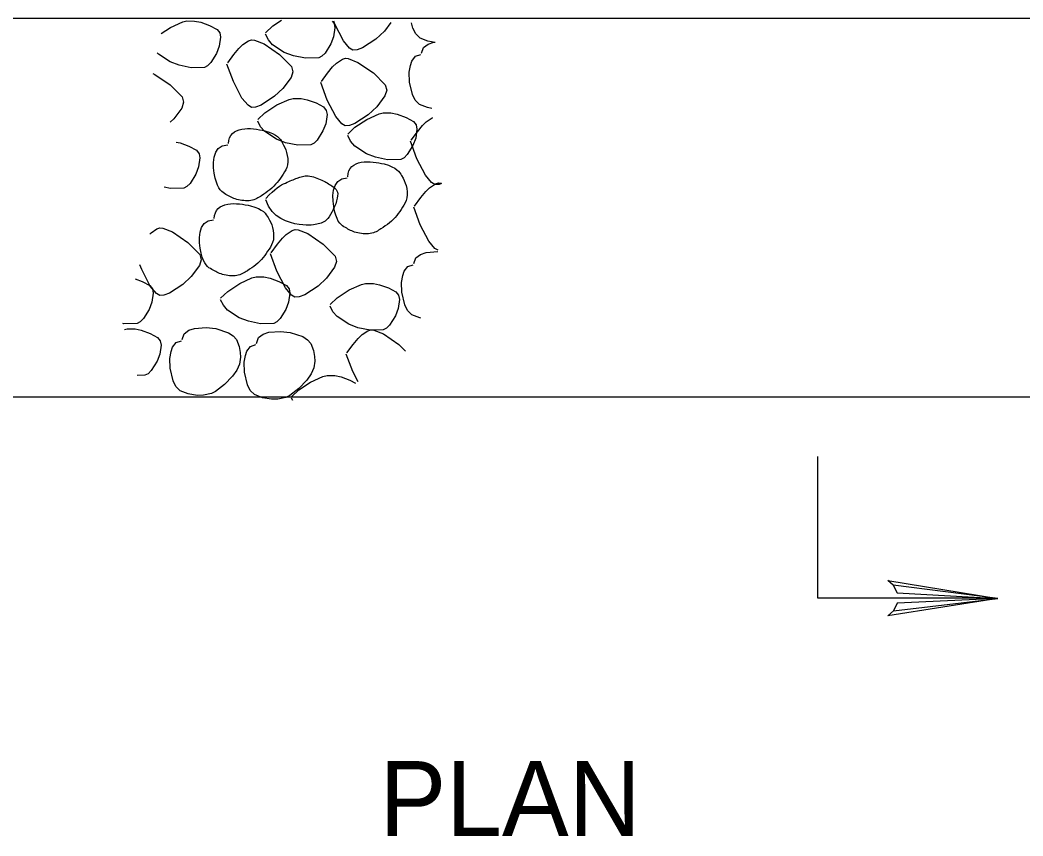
# Model space of a CAD drawing. Extents: x 636462 to 638208, y 299350 to 300538.
# Drawn here: x 637731.8 to 637790.4, y 299698.3 to 299746 of the extents above; entities that cross this region are included whole.
import ezdxf

# ---------------------------------------------------------------- set-up
doc = ezdxf.new("R2010")
doc.units = 0
doc.layers.add('Default', color=7, linetype='Continuous')

# ---------------------------------------------------------------- blocks, each defined once
blk = doc.blocks.new('SC9446')
at = {"layer": 'Default'}
blk.add_line((0, 0), (0, 0), dxfattribs=at)

msp = doc.modelspace()

# ---------------------------------------------------------------- linework, layer by layer
at = {"layer": 'Default'}
for p, q in [((637740.02, 299745.161), (637740.557, 299745.518)), ((637740.557, 299745.518), (637741.275, 299745.843)), ((637741.275, 299745.843), (637741.513, 299745.901)), ((637741.513, 299745.901), (637741.971, 299745.896)), ((637741.971, 299745.896), (637742.33, 299745.822)), ((637742.33, 299745.822), (637742.851, 299745.633)), ((637742.851, 299745.633), (637743.286, 299745.396)), ((637746.121, 299745.214), (637746.536, 299745.613)), ((637746.536, 299745.613), (637747.038, 299745.944)), ((637750.014, 299745.882), (637750.115, 299745.756)), ((637750.164, 299745.507), (637750.088, 299744.977)), ((637750.164, 299745.703), (637750.097, 299745.88)), ((637750.115, 299745.756), (637750.164, 299745.507)), ((637750.666, 299744.742), (637750.164, 299745.703)), ((637753.439, 299745.811), (637753.061, 299745.3)), ((637754.717, 299745.475), (637754.643, 299745.786)), ((637754.887, 299745.143), (637754.717, 299745.475)), ((637743.286, 299745.396), (637743.44, 299745.2)), ((637743.489, 299744.952), (637743.413, 299744.422)), ((637743.44, 299745.2), (637743.489, 299744.952)), ((637746.283, 299744.8), (637746.121, 299745.124)), ((637750.088, 299744.977), (637749.929, 299744.558)), ((637753.061, 299745.3), (637752.563, 299744.843)), ((637755.138, 299744.894), (637754.887, 299745.143)), ((637755.592, 299744.71), (637755.138, 299744.894)), ((637743.413, 299744.422), (637743.254, 299744.003)), ((637744.263, 299743.936), (637744.555, 299744.288)), ((637744.555, 299744.288), (637744.781, 299744.516)), ((637744.781, 299744.516), (637745.126, 299744.744)), ((637745.126, 299744.744), (637745.297, 299744.793)), ((637745.297, 299744.793), (637745.465, 299744.786)), ((637745.465, 299744.786), (637746.029, 299744.558)), ((637746.029, 299744.558), (637746.932, 299743.938)), ((637746.529, 299744.514), (637746.283, 299744.8)), ((637747.211, 299744.067), (637746.529, 299744.514)), ((637749.929, 299744.558), (637749.592, 299744.019)), ((637751.018, 299744.316), (637750.666, 299744.742)), ((637751.214, 299744.201), (637751.018, 299744.316)), ((637751.785, 299744.332), (637751.458, 299744.208)), ((637752.563, 299744.843), (637751.785, 299744.332)), ((637755.228, 299744.012), (637755.35, 299744.348)), ((637755.35, 299744.348), (637755.618, 299744.551)), ((637756.016, 299744.641), (637755.592, 299744.71)), ((637755.618, 299744.551), (637755.942, 299744.662)), ((637755.942, 299744.662), (637756.016, 299744.666)), ((637739.854, 299743.959), (637739.783, 299744.042)), ((637740.536, 299743.515), (637739.854, 299743.959)), ((637743.254, 299744.003), (637742.918, 299743.464)), ((637743.903, 299743.445), (637744.263, 299743.936)), ((637746.932, 299743.938), (637747.63, 299743.245)), ((637747.741, 299743.867), (637747.211, 299744.067)), ((637748.448, 299743.717), (637747.741, 299743.867)), ((637749.224, 299743.74), (637748.448, 299743.717)), ((637749.408, 299743.837), (637749.224, 299743.74)), ((637749.592, 299744.019), (637749.408, 299743.837)), ((637750.606, 299743.669), (637750.776, 299743.717)), ((637750.776, 299743.717), (637750.947, 299743.71)), ((637750.947, 299743.71), (637751.511, 299743.482)), ((637751.458, 299744.208), (637751.214, 299744.201)), ((637754.666, 299743.561), (637754.878, 299743.837)), ((637754.878, 299743.837), (637755.182, 299743.945)), ((637741.066, 299743.312), (637740.536, 299743.515)), ((637741.773, 299743.162), (637741.066, 299743.312)), ((637742.549, 299743.185), (637741.773, 299743.162)), ((637742.731, 299743.282), (637742.549, 299743.185)), ((637742.918, 299743.464), (637742.731, 299743.282)), ((637744.237, 299742.358), (637743.857, 299743.379)), ((637747.63, 299743.245), (637747.713, 299742.93)), ((637749.742, 299742.86), (637750.035, 299743.215)), ((637750.035, 299743.215), (637750.263, 299743.441)), ((637750.263, 299743.441), (637750.606, 299743.669)), ((637751.511, 299743.482), (637752.414, 299742.865)), ((637754.512, 299742.911), (637754.576, 299743.307)), ((637754.576, 299743.307), (637754.666, 299743.561)), ((637739.527, 299742.828), (637739.649, 299742.78)), ((637739.649, 299742.78), (637740.552, 299742.16)), ((637747.607, 299742.596), (637747.132, 299741.955)), ((637747.713, 299742.93), (637747.607, 299742.596)), ((637749.383, 299742.37), (637749.742, 299742.86)), ((637752.414, 299742.865), (637753.112, 299742.169)), ((637754.524, 299742.333), (637754.512, 299742.911)), ((637740.552, 299742.16), (637741.25, 299741.465)), ((637744.739, 299741.398), (637744.237, 299742.358)), ((637747.132, 299741.955), (637746.637, 299741.499)), ((637749.717, 299741.283), (637749.339, 299742.303)), ((637753.112, 299742.169), (637753.192, 299741.854)), ((637754.696, 299741.601), (637754.524, 299742.333)), ((637741.25, 299741.465), (637741.331, 299741.151)), ((637745.092, 299740.972), (637744.739, 299741.398)), ((637746.637, 299741.499), (637745.859, 299740.988)), ((637747.494, 299741.322), (637747.729, 299741.379)), ((637747.729, 299741.379), (637748.19, 299741.375)), ((637748.19, 299741.375), (637748.549, 299741.301)), ((637753.086, 299741.52), (637752.614, 299740.88)), ((637753.192, 299741.854), (637753.086, 299741.52)), ((637754.864, 299741.269), (637754.696, 299741.601)), ((637741.225, 299740.815), (637740.753, 299740.177)), ((637741.331, 299741.151), (637741.225, 299740.815)), ((637745.288, 299740.854), (637745.092, 299740.972)), ((637745.529, 299740.861), (637745.288, 299740.854)), ((637745.859, 299740.988), (637745.529, 299740.861)), ((637746.08, 299740.536), (637746.775, 299740.997)), ((637746.775, 299740.997), (637747.494, 299741.322)), ((637748.549, 299741.301), (637749.067, 299741.112)), ((637749.067, 299741.112), (637749.502, 299740.875)), ((637749.502, 299740.875), (637749.659, 299740.679)), ((637750.219, 299740.322), (637749.717, 299741.283)), ((637752.614, 299740.88), (637752.117, 299740.424)), ((637755.115, 299741.02), (637754.864, 299741.269)), ((637755.569, 299740.836), (637755.115, 299741.02)), ((637755.823, 299740.794), (637755.569, 299740.836)), ((637740.753, 299740.177), (637740.552, 299739.993)), ((637745.663, 299740.138), (637746.08, 299740.536)), ((637749.705, 299740.433), (637749.629, 299739.901)), ((637749.659, 299740.679), (637749.705, 299740.433)), ((637750.571, 299739.896), (637750.219, 299740.322)), ((637752.117, 299740.424), (637751.34, 299739.912)), ((637752.029, 299740.147), (637752.75, 299740.472)), ((637752.75, 299740.472), (637752.985, 299740.532)), ((637752.985, 299740.532), (637753.443, 299740.527)), ((637753.443, 299740.527), (637753.805, 299740.451)), ((637753.805, 299740.451), (637754.323, 299740.262)), ((637754.323, 299740.262), (637754.758, 299740.025)), ((637755.505, 299740.011), (637755.848, 299740.239)), ((637755.848, 299740.239), (637755.894, 299740.253)), ((637745.824, 299739.723), (637745.663, 299740.048)), ((637746.073, 299739.438), (637745.824, 299739.723)), ((637749.629, 299739.901), (637749.47, 299739.482)), ((637750.767, 299739.781), (637750.571, 299739.896)), ((637751.011, 299739.786), (637750.767, 299739.781)), ((637750.919, 299739.29), (637751.334, 299739.687)), ((637751.34, 299739.912), (637751.011, 299739.786)), ((637751.334, 299739.687), (637752.029, 299740.147)), ((637754.758, 299740.025), (637754.913, 299739.829)), ((637754.961, 299739.583), (637754.885, 299739.053)), ((637754.913, 299739.829), (637754.961, 299739.583)), ((637754.986, 299739.431), (637755.277, 299739.786)), ((637755.277, 299739.786), (637755.505, 299740.011)), ((637746.755, 299738.993), (637746.073, 299739.438)), ((637747.284, 299738.791), (637746.755, 299738.993)), ((637749.47, 299739.482), (637749.136, 299738.943)), ((637751.08, 299738.876), (637750.919, 299739.201)), ((637754.625, 299738.94), (637754.986, 299739.431)), ((637754.885, 299739.053), (637754.726, 299738.634)), ((637740.886, 299738.821), (637741.123, 299738.772)), ((637741.123, 299738.772), (637741.642, 299738.581)), ((637741.642, 299738.581), (637742.077, 299738.346)), ((637747.992, 299738.641), (637747.284, 299738.791)), ((637748.768, 299738.664), (637747.992, 299738.641)), ((637748.95, 299738.761), (637748.768, 299738.664)), ((637749.136, 299738.943), (637748.95, 299738.761)), ((637751.327, 299738.59), (637751.08, 299738.876)), ((637752.008, 299738.143), (637751.327, 299738.59)), ((637754.726, 299738.634), (637754.392, 299738.095)), ((637754.959, 299737.853), (637754.581, 299738.874)), ((637742.077, 299738.346), (637742.234, 299738.148)), ((637742.28, 299737.902), (637742.204, 299737.372)), ((637742.234, 299738.148), (637742.28, 299737.902)), ((637752.538, 299737.941), (637752.008, 299738.143)), ((637753.248, 299737.791), (637752.538, 299737.941)), ((637754.021, 299737.816), (637753.248, 299737.791)), ((637754.206, 299737.911), (637754.021, 299737.816)), ((637754.392, 299738.095), (637754.206, 299737.911)), ((637755.461, 299736.893), (637754.959, 299737.853)), ((637742.204, 299737.372), (637742.045, 299736.953)), ((637742.045, 299736.953), (637741.711, 299736.414)), ((637755.813, 299736.467), (637755.461, 299736.893)), ((637740.566, 299736.112), (637740.186, 299736.19)), ((637741.34, 299736.135), (637740.566, 299736.112)), ((637741.524, 299736.232), (637741.34, 299736.135)), ((637741.711, 299736.414), (637741.524, 299736.232)), ((637755.472, 299735.932), (637755.7, 299736.158)), ((637755.7, 299736.158), (637756.044, 299736.388)), ((637756.009, 299736.351), (637755.813, 299736.467)), ((637756.253, 299736.356), (637756.009, 299736.351)), ((637756.044, 299736.388), (637756.214, 299736.437)), ((637756.214, 299736.437), (637756.385, 299736.43)), ((637756.396, 299736.411), (637756.253, 299736.356)), ((637756.385, 299736.43), (637756.394, 299736.425)), ((637754.821, 299735.089), (637755.182, 299735.58)), ((637755.182, 299735.58), (637755.472, 299735.932)), ((637755.155, 299734.002), (637754.777, 299735.023)), ((637739.428, 299733.532), (637739.771, 299733.76)), ((637739.771, 299733.76), (637739.944, 299733.809)), ((637739.944, 299733.809), (637740.112, 299733.802)), ((637740.112, 299733.802), (637740.677, 299733.574)), ((637755.657, 299733.042), (637755.155, 299734.002)), ((637739.352, 299733.456), (637739.428, 299733.532)), ((637740.677, 299733.574), (637741.579, 299732.957)), ((637746.808, 299732.855), (637747.1, 299733.208)), ((637747.1, 299733.208), (637747.328, 299733.433)), ((637747.328, 299733.433), (637747.671, 299733.664)), ((637747.671, 299733.664), (637747.842, 299733.71)), ((637747.842, 299733.71), (637748.012, 299733.703)), ((637748.012, 299733.703), (637748.577, 299733.477)), ((637748.577, 299733.477), (637749.479, 299732.858)), ((637741.579, 299732.957), (637742.277, 299732.261)), ((637746.448, 299732.362), (637746.808, 299732.855)), ((637749.479, 299732.858), (637750.177, 299732.162)), ((637756.009, 299732.616), (637755.657, 299733.042)), ((637756.196, 299732.505), (637756.009, 299732.616)), ((637742.277, 299732.261), (637742.36, 299731.945)), ((637746.782, 299731.277), (637746.405, 299732.296)), ((637750.177, 299732.162), (637750.258, 299731.849)), ((637754.777, 299731.729), (637754.897, 299732.065)), ((637754.897, 299732.065), (637755.166, 299732.268)), ((637755.166, 299732.268), (637755.491, 299732.376)), ((637755.491, 299732.376), (637756.186, 299732.431)), ((637738.885, 299731.374), (637738.776, 299731.664)), ((637739.384, 299730.414), (637738.885, 299731.374)), ((637742.254, 299731.611), (637741.78, 299730.971)), ((637742.36, 299731.945), (637742.254, 299731.611)), ((637750.152, 299731.512), (637749.68, 299730.874)), ((637750.258, 299731.849), (637750.152, 299731.512)), ((637754.215, 299731.277), (637754.427, 299731.554)), ((637754.427, 299731.554), (637754.731, 299731.662)), ((637738.509, 299730.831), (637738.917, 299730.683)), ((637741.78, 299730.971), (637741.285, 299730.515)), ((637744.604, 299730.568), (637745.322, 299730.893)), ((637745.322, 299730.893), (637745.559, 299730.95)), ((637745.559, 299730.95), (637746.018, 299730.946)), ((637746.018, 299730.946), (637746.379, 299730.872)), ((637746.379, 299730.872), (637746.898, 299730.683)), ((637747.284, 299730.317), (637746.782, 299731.277)), ((637749.68, 299730.874), (637749.182, 299730.416)), ((637754.061, 299730.628), (637754.125, 299731.024)), ((637754.125, 299731.024), (637754.215, 299731.277)), ((637738.917, 299730.683), (637739.352, 299730.446)), ((637739.352, 299730.446), (637739.506, 299730.25)), ((637739.739, 299729.988), (637739.384, 299730.414)), ((637739.506, 299730.25), (637739.555, 299730.004)), ((637741.285, 299730.515), (637740.506, 299730.004)), ((637743.908, 299730.107), (637744.604, 299730.568)), ((637746.898, 299730.683), (637747.333, 299730.446)), ((637747.637, 299729.891), (637747.284, 299730.317)), ((637747.333, 299730.446), (637747.487, 299730.25)), ((637747.487, 299730.25), (637747.536, 299730.004)), ((637749.182, 299730.416), (637748.406, 299729.905)), ((637751.002, 299730.193), (637751.72, 299730.517)), ((637751.72, 299730.517), (637751.958, 299730.575)), ((637751.958, 299730.575), (637752.416, 299730.57)), ((637752.416, 299730.57), (637752.775, 299730.497)), ((637752.775, 299730.497), (637753.296, 299730.308)), ((637753.296, 299730.308), (637753.731, 299730.071)), ((637754.072, 299730.05), (637754.061, 299730.628)), ((637739.555, 299730.004), (637739.479, 299729.472)), ((637739.933, 299729.87), (637739.739, 299729.988)), ((637740.177, 299729.877), (637739.933, 299729.87)), ((637740.506, 299730.004), (637740.177, 299729.877)), ((637743.493, 299729.709), (637743.908, 299730.107)), ((637743.655, 299729.294), (637743.493, 299729.619)), ((637747.536, 299730.004), (637747.46, 299729.472)), ((637747.833, 299729.773), (637747.637, 299729.891)), ((637748.077, 299729.78), (637747.833, 299729.773)), ((637748.406, 299729.905), (637748.077, 299729.78)), ((637749.889, 299729.334), (637750.306, 299729.732)), ((637750.306, 299729.732), (637751.002, 299730.193)), ((637753.731, 299730.071), (637753.886, 299729.875)), ((637753.934, 299729.628), (637753.858, 299729.096)), ((637753.886, 299729.875), (637753.934, 299729.628)), ((637754.243, 299729.317), (637754.072, 299730.05)), ((637739.32, 299729.053), (637738.986, 299728.514)), ((637739.479, 299729.472), (637739.32, 299729.053)), ((637743.901, 299729.009), (637743.655, 299729.294)), ((637747.301, 299729.053), (637746.967, 299728.514)), ((637747.46, 299729.472), (637747.301, 299729.053)), ((637750.051, 299728.919), (637749.889, 299729.244)), ((637753.858, 299729.096), (637753.699, 299728.677)), ((637754.413, 299728.983), (637754.243, 299729.317)), ((637738.986, 299728.514), (637738.799, 299728.332)), ((637744.583, 299728.564), (637743.901, 299729.009)), ((637745.113, 299728.362), (637744.583, 299728.564)), ((637746.967, 299728.514), (637746.78, 299728.332)), ((637750.299, 299728.633), (637750.051, 299728.919)), ((637750.981, 299728.189), (637750.299, 299728.633)), ((637753.699, 299728.677), (637753.363, 299728.138)), ((637754.664, 299728.737), (637754.413, 299728.983)), ((637755.118, 299728.553), (637754.664, 299728.737)), ((637755.191, 299728.541), (637755.118, 299728.553)), ((637737.839, 299728.212), (637737.779, 299728.226)), ((637738.615, 299728.235), (637737.839, 299728.212)), ((637737.876, 299727.878), (637738.035, 299727.919)), ((637738.035, 299727.919), (637738.495, 299727.915)), ((637738.495, 299727.915), (637738.855, 299727.839)), ((637738.799, 299728.332), (637738.615, 299728.235)), ((637741.635, 299727.832), (637741.962, 299727.94)), ((637741.962, 299727.94), (637742.655, 299727.995)), ((637742.655, 299727.995), (637743.21, 299727.931)), ((637743.21, 299727.931), (637743.954, 299727.689)), ((637745.822, 299728.212), (637745.113, 299728.362)), ((637746.596, 299728.235), (637745.822, 299728.212)), ((637746.78, 299728.332), (637746.596, 299728.235)), ((637751.511, 299727.986), (637750.981, 299728.189)), ((637752.218, 299727.836), (637751.511, 299727.986)), ((637752.994, 299727.86), (637752.218, 299727.836)), ((637753.178, 299727.956), (637752.994, 299727.86)), ((637753.363, 299728.138), (637753.178, 299727.956)), ((637738.855, 299727.839), (637739.373, 299727.65)), ((637739.373, 299727.65), (637739.808, 299727.413)), ((637739.808, 299727.413), (637739.965, 299727.217)), ((637741.245, 299727.293), (637741.368, 299727.629)), ((637741.368, 299727.629), (637741.635, 299727.832)), ((637743.954, 299727.689), (637744.233, 299727.507)), ((637744.233, 299727.507), (637744.417, 299727.293)), ((637744.417, 299727.293), (637744.574, 299726.89)), ((637745.587, 299727.065), (637745.709, 299727.403)), ((637745.709, 299727.403), (637745.976, 299727.604)), ((637745.976, 299727.604), (637746.303, 299727.714)), ((637746.303, 299727.714), (637746.997, 299727.77)), ((637746.997, 299727.77), (637747.552, 299727.705)), ((637747.552, 299727.705), (637748.296, 299727.461)), ((637748.296, 299727.461), (637748.574, 299727.281)), ((637748.574, 299727.281), (637748.759, 299727.065)), ((637751.232, 299726.998), (637751.525, 299727.353)), ((637751.525, 299727.353), (637751.75, 299727.579)), ((637751.75, 299727.579), (637752.094, 299727.807)), ((637752.094, 299727.807), (637752.266, 299727.855)), ((637752.266, 299727.855), (637752.434, 299727.848)), ((637752.434, 299727.848), (637752.999, 299727.62)), ((637752.999, 299727.62), (637753.902, 299727)), ((637740.011, 299726.97), (637739.935, 299726.441)), ((637739.965, 299727.217), (637740.011, 299726.97)), ((637740.594, 299726.588), (637740.686, 299726.841)), ((637740.686, 299726.841), (637740.895, 299727.118)), ((637740.895, 299727.118), (637741.202, 299727.226)), ((637744.574, 299726.89), (637744.636, 299726.535)), ((637745.027, 299726.616), (637745.237, 299726.892)), ((637745.237, 299726.892), (637745.543, 299726.998)), ((637748.759, 299727.065), (637748.915, 299726.662)), ((637750.871, 299726.508), (637751.232, 299726.998)), ((637753.902, 299727), (637754.293, 299726.613)), ((637739.935, 299726.441), (637739.776, 299726.022)), ((637740.531, 299726.192), (637740.594, 299726.588)), ((637740.543, 299725.614), (637740.531, 299726.192)), ((637744.645, 299726.259), (637744.59, 299725.858)), ((637744.636, 299726.535), (637744.645, 299726.259)), ((637744.871, 299725.966), (637744.935, 299726.362)), ((637744.935, 299726.362), (637745.027, 299726.616)), ((637748.915, 299726.662), (637748.977, 299726.307)), ((637748.977, 299726.307), (637748.987, 299726.033)), ((637751.207, 299725.42), (637750.827, 299726.441)), ((637739.776, 299726.022), (637739.442, 299725.483)), ((637740.713, 299724.881), (637740.543, 299725.614)), ((637744.59, 299725.858), (637744.44, 299725.506)), ((637744.885, 299725.388), (637744.871, 299725.966)), ((637748.931, 299725.632), (637748.779, 299725.28)), ((637748.987, 299726.033), (637748.931, 299725.632)), ((637739.071, 299725.204), (637738.622, 299725.19)), ((637739.255, 299725.298), (637739.071, 299725.204)), ((637739.442, 299725.483), (637739.255, 299725.298)), ((637744.177, 299725.149), (637743.714, 299724.663)), ((637744.44, 299725.506), (637744.177, 299725.149)), ((637745.055, 299724.656), (637744.885, 299725.388)), ((637748.779, 299725.28), (637748.519, 299724.923)), ((637748.749, 299724.81), (637749.468, 299725.135)), ((637749.468, 299725.135), (637749.705, 299725.192)), ((637749.705, 299725.192), (637750.164, 299725.188)), ((637750.164, 299725.188), (637750.523, 299725.114)), ((637750.523, 299725.114), (637751.043, 299724.925)), ((637751.518, 299724.822), (637751.207, 299725.42)), ((637740.884, 299724.547), (637740.713, 299724.881)), ((637741.135, 299724.301), (637740.884, 299724.547)), ((637743.714, 299724.663), (637743.189, 299724.255)), ((637745.225, 299724.322), (637745.055, 299724.656)), ((637748.056, 299724.437), (637747.529, 299724.029)), ((637747.637, 299723.951), (637748.054, 299724.349)), ((637748.054, 299724.349), (637748.749, 299724.81)), ((637748.519, 299724.923), (637748.056, 299724.437)), ((637751.043, 299724.925), (637751.373, 299724.746)), ((637741.589, 299724.117), (637741.135, 299724.301)), ((637742.128, 299724.027), (637741.589, 299724.117)), ((637742.498, 299724.034), (637742.128, 299724.027)), ((637742.959, 299724.14), (637742.498, 299724.034)), ((637743.189, 299724.255), (637742.959, 299724.14)), ((637745.476, 299724.073), (637745.225, 299724.322)), ((637745.93, 299723.891), (637745.476, 299724.073)), ((637746.469, 299723.801), (637745.93, 299723.891)), ((637746.838, 299723.808), (637746.469, 299723.801)), ((637747.301, 299723.914), (637746.838, 299723.808)), ((637747.529, 299724.029), (637747.301, 299723.914)), ((637747.701, 299723.734), (637747.637, 299723.861))]:
    msp.add_line(p, q, dxfattribs=at)
for points in [[(637698.562, 299746.05), (637698.562, 299723.939), (637836.756, 299723.939), (637836.756, 299746.05), (637698.562, 299746.05)], [(637788.617, 299712.179), (637778.373, 299712.179), (637778.373, 299720.471)], [(637782.782, 299712.944), (637783.009, 299712.502), (637788.884, 299712.177), (637782.782, 299712.944), (637782.469, 299713.211), (637788.884, 299712.177), (637783.014, 299711.887), (637782.799, 299711.45), (637788.884, 299712.177), (637782.469, 299711.158), (637782.799, 299711.45)]]:
    msp.add_lwpolyline(points, dxfattribs=at)
for points in [[(637743.949, 299738.74), (637743.963, 299739.797), (637746.668, 299739.558), (637747.121, 299738.74), (637747.376, 299738.28), (637747.467, 299737.449), (637747.144, 299736.955), (637746.824, 299736.465), (637746.382, 299736.022), (637745.893, 299735.704), (637745.326, 299735.335), (637744.362, 299735.447), (637743.839, 299735.748), (637743.094, 299736.176), (637742.931, 299738.65), (637743.906, 299738.673)], [(637750.924, 299736.805), (637750.937, 299737.862), (637753.642, 299737.623), (637754.095, 299736.805), (637754.351, 299736.344), (637754.441, 299735.513), (637754.118, 299735.018), (637753.798, 299734.528), (637753.356, 299734.085), (637752.868, 299733.767), (637752.3, 299733.398), (637751.336, 299733.512), (637750.813, 299733.813), (637750.068, 299734.242), (637749.906, 299736.713), (637750.88, 299736.736)], [(637746.137, 299735.536), (637746.654, 299736.12), (637747.339, 299736.483), (637747.966, 299736.72), (637748.56, 299736.945), (637749.472, 299736.603), (637749.977, 299736.273), (637750.548, 299735.9), (637749.792, 299734.203), (637749.24, 299734.062), (637748.435, 299733.857), (637746.489, 299734.356), (637746.137, 299735.446)], [(637743.123, 299734.357), (637743.136, 299735.414), (637745.841, 299735.175), (637746.294, 299734.357), (637746.55, 299733.896), (637746.64, 299733.064), (637746.317, 299732.57), (637745.997, 299732.08), (637745.555, 299731.637), (637745.066, 299731.319), (637744.499, 299730.95), (637743.535, 299731.064), (637743.012, 299731.365), (637742.267, 299731.794), (637742.104, 299734.269), (637743.079, 299734.29)]]:
    msp.add_open_spline(points, degree=3, dxfattribs=at)

# ---------------------------------------------------------------- block references
at = {"layer": 'Default', "xscale": 3.0226054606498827, "yscale": 3.0226054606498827}
msp.add_blockref('SC9446', (637756.187, 299732.431), dxfattribs=at)

# ---------------------------------------------------------------- texts
at = {"layer": 'Default'}
msp.add_text('PLAN', height=4.3721, dxfattribs=at).set_placement((637752.772, 299698.299))

doc.saveas('drawing.dxf')
